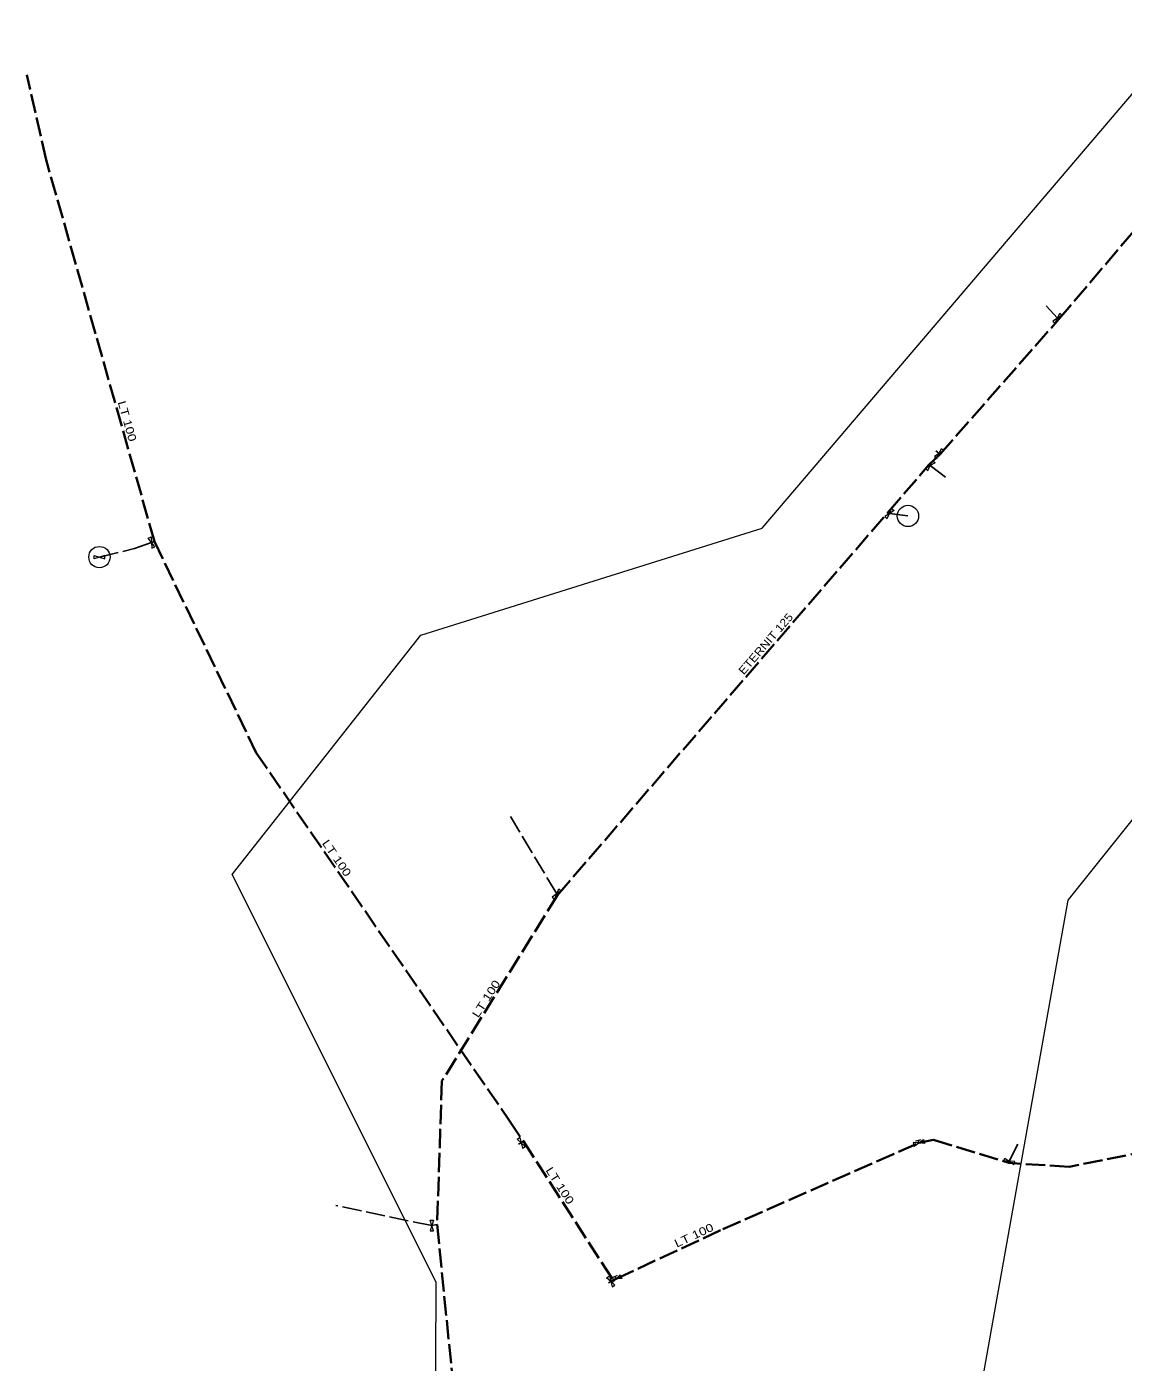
# Model space of a CAD drawing. Extents: x -616592 to -615844, y -1088988 to -1088174.
# Drawn here: x -616355.3 to -616252.5, y -1088630.7 to -1088505.5 of the extents above; entities that cross this region are included whole.
import ezdxf
from ezdxf.enums import TextEntityAlignment as Align

# ---------------------------------------------------------------- set-up
doc = ezdxf.new("R2010")
doc.units = 0
doc.header["$LTSCALE"] = 0.3
doc.linetypes.add('LONG_DASHED', pattern=[7.5, 6, -1.5])
for name, color, linetype, lineweight in [('1', 7, 'Continuous', 13), ('10', 7, 'Continuous', 13), ('35', 7, 'LONG_DASHED', 35), ('50', 7, 'LONG_DASHED', 25)]:
    doc.layers.add(name, color=color, linetype=linetype, lineweight=lineweight)
doc.layers.add('16', color=7, linetype='Continuous')

msp = doc.modelspace()

# ---------------------------------------------------------------- linework, layer by layer
at = {"layer": '1'}
msp.add_lwpolyline([(-616317.402, -1088743.479), (-616316.925, -1088623.142), (-616336.026, -1088584.94), (-616318.357, -1088562.497), (-616286.363, -1088552.469), (-616214.734, -1088468.424), (-616144.06, -1088425.447), (-616043.302, -1088392.02), (-615921.533, -1088342.835), (-615901, -1088273.116), (-615900.045, -1088185.251), (-615900.045, -1088185.251), (-615851.337, -1088190.027), (-615863.753, -1088293.172), (-615879.033, -1088367.189), (-615932.994, -1088397.75), (-616036.139, -1088431.177), (-616143.105, -1088462.216), (-616202.318, -1088518.087), (-616257.711, -1088587.328), (-616274.902, -1088683.788)], dxfattribs=at)
at = {"layer": '10'}
for p, q in [((-616271.733, -1088609.849), (-616271.974, -1088609.917)), ((-616300.145, -1088622.605), (-616300.372, -1088622.71))]:
    msp.add_line(p, q, dxfattribs=at)
for points in [[(-616258.668, -1088532.786), (-616258.453, -1088532.31), (-616258.227, -1088532.507), (-616258.668, -1088532.786), (-616259.109, -1088533.065), (-616258.883, -1088533.262)], [(-616269.757, -1088545.473), (-616269.535, -1088545.001), (-616269.311, -1088545.201), (-616269.757, -1088545.473), (-616270.203, -1088545.745), (-616269.979, -1088545.945)], [(-616270.6, -1088546.605), (-616270.369, -1088546.137), (-616270.149, -1088546.341), (-616270.6, -1088546.605), (-616271.051, -1088546.869), (-616270.831, -1088547.073)], [(-616274.426, -1088551.082), (-616274.214, -1088550.605), (-616273.986, -1088550.8), (-616274.426, -1088551.082), (-616274.866, -1088551.364), (-616274.638, -1088551.559)], [(-616343.586, -1088553.807), (-616343.896, -1088553.387), (-616343.614, -1088553.286), (-616343.586, -1088553.807), (-616343.558, -1088554.328), (-616343.276, -1088554.227)], [(-616348.47, -1088555.18), (-616348.97, -1088555.33), (-616348.97, -1088555.03), (-616348.47, -1088555.18), (-616347.97, -1088555.33), (-616347.97, -1088555.03)], [(-616305.606, -1088586.747), (-616305.416, -1088586.261), (-616305.18, -1088586.445), (-616305.606, -1088586.747), (-616306.032, -1088587.049), (-616305.796, -1088587.233)], [(-616308.943, -1088610.082), (-616309.331, -1088609.732), (-616309.074, -1088609.577), (-616308.943, -1088610.082), (-616308.812, -1088610.587), (-616308.555, -1088610.432)], [(-616263.187, -1088611.812), (-616263.709, -1088611.806), (-616263.619, -1088611.52), (-616263.187, -1088611.812), (-616262.755, -1088612.104), (-616262.665, -1088611.818)], [(-616317.317, -1088617.848), (-616317.467, -1088617.348), (-616317.167, -1088617.348), (-616317.317, -1088617.848), (-616317.467, -1088618.348), (-616317.167, -1088618.348)], [(-616300.551, -1088623.084), (-616300.934, -1088622.729), (-616300.675, -1088622.577), (-616300.551, -1088623.084), (-616300.427, -1088623.591), (-616300.168, -1088623.439)]]:
    msp.add_lwpolyline(points, close=True, dxfattribs=at)
for points in [[(-616271.665, -1088610.089), (-616271.235, -1088609.772), (-616271.133, -1088610.132), (-616271.665, -1088610.089), (-616272.197, -1088610.046), (-616272.095, -1088610.406), (-616271.665, -1088610.089), (-616271.733, -1088609.849), (-616271.493, -1088609.78)], [(-616300.04, -1088622.832), (-616299.665, -1088622.452), (-616299.508, -1088622.791), (-616300.04, -1088622.832), (-616300.572, -1088622.873), (-616300.415, -1088623.212), (-616300.04, -1088622.832), (-616300.145, -1088622.605), (-616299.918, -1088622.5)]]:
    msp.add_lwpolyline(points, dxfattribs=at)
for centre in [(-616272.683, -1088551.313), (-616348.47, -1088555.18)]:
    msp.add_circle(centre, 1, dxfattribs=at)
at = {"layer": '35'}
for p, q in [((-616258.554, -1088532.884), (-616239.896, -1088510.962)), ((-616269.68, -1088545.527), (-616258.554, -1088532.884)), ((-616270.716, -1088546.515), (-616269.68, -1088545.527)), ((-616274.535, -1088550.96), (-616270.716, -1088546.515)), ((-616305.525, -1088586.853), (-616274.535, -1088550.96)), ((-616308.734, -1088609.94), (-616300.32, -1088622.954)), ((-616316.823, -1088617.753), (-616312.654, -1088659.097)), ((-616300.32, -1088622.954), (-616300.04, -1088622.832))]:
    msp.add_line(p, q, dxfattribs=at)
for points in [[(-616343.316, -1088553.714), (-616353.473, -1088517.921), (-616355.29, -1088509.982)], [(-616343.316, -1088553.714), (-616333.784, -1088573.514), (-616310.037, -1088608.017), (-616308.734, -1088609.94)], [(-616305.525, -1088586.853), (-616316.37, -1088604.279), (-616316.823, -1088617.753)], [(-616300.04, -1088622.832), (-616290.041, -1088618.181), (-616271.665, -1088610.089)], [(-616271.665, -1088610.089), (-616270.286, -1088609.794), (-616263.226, -1088611.964)], [(-616250.043, -1088610.816), (-616257.588, -1088612.33), (-616263.226, -1088611.964)]]:
    msp.add_lwpolyline(points, dxfattribs=at)
at = {"layer": '50'}
for p, q in [((-616258.668, -1088532.786), (-616259.72, -1088531.629)), ((-616258.554, -1088532.884), (-616258.668, -1088532.786)), ((-616269.757, -1088545.473), (-616270.063, -1088545.228)), ((-616269.68, -1088545.527), (-616269.757, -1088545.473)), ((-616270.716, -1088546.515), (-616270.6, -1088546.605)), ((-616270.6, -1088546.605), (-616269.069, -1088547.758)), ((-616274.535, -1088550.96), (-616274.426, -1088551.082)), ((-616274.426, -1088551.082), (-616272.683, -1088551.313)), ((-616348.47, -1088555.18), (-616345.173, -1088554.376)), ((-616343.586, -1088553.807), (-616345.173, -1088554.376)), ((-616343.316, -1088553.714), (-616343.586, -1088553.807)), ((-616305.606, -1088586.747), (-616309.95, -1088579.506)), ((-616305.525, -1088586.853), (-616305.606, -1088586.747)), ((-616308.943, -1088610.082), (-616309.177, -1088610.214)), ((-616308.734, -1088609.94), (-616308.943, -1088610.082)), ((-616263.187, -1088611.812), (-616262.386, -1088610.177)), ((-616263.226, -1088611.964), (-616263.187, -1088611.812)), ((-616300.551, -1088623.084), (-616300.747, -1088623.217)), ((-616300.32, -1088622.954), (-616300.551, -1088623.084))]:
    msp.add_line(p, q, dxfattribs=at)
msp.add_lwpolyline([(-616316.823, -1088617.753), (-616317.317, -1088617.848), (-616326.322, -1088615.953)], dxfattribs=at)

# ---------------------------------------------------------------- texts
at = {"layer": '16'}
for s, rotation, width, p in [('LT 100', 285.842, 1.25, (-616346.2294, -1088542.5316)), ('ETERNIT 125', 49.193, 1.15, (-616285.7336, -1088563.5481)), ('LT 100', 304.538, 1.25, (-616326.5386, -1088583.6019)), ('LT 100', 57.27, 1.25, (-616311.9122, -1088596.7803)), ('LT 100', 302.884, 1.25, (-616305.6236, -1088614.2909)), ('LT 100', 24.945, 1.25, (-616292.5907, -1088619.0911))]:
    msp.add_text(s, height=0.75, rotation=rotation, dxfattribs=dict(at, width=width)).set_placement(p, align=Align.CENTER)

doc.saveas('drawing.dxf')
